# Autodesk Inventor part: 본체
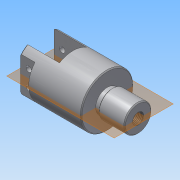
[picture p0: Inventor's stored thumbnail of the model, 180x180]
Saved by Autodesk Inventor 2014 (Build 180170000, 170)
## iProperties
Created: 2019-02
Part Number: 본체
Material: 알루미늄 6061
Document SubType Name: Modeling
Designer: net
Mass: 347.664 g
Surface Area: 292.638 cm^2
Volume: 128.289 cm^3
Density: 2.71 g/cm^3
Appearance: 알루미늄 - 평지
Author: net
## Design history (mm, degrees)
sketch "스케치1"
  geometry: L1 (0, 0)-(38, 0); L2 (0, 29)-(38, 29); L3 (38, 29)-(38, 0); L4 (0, 29)-(0, 14); L5 (0, 14)-(2.65, 14); L6 (2.65, 14)-(2.65, 17); L7 (2.65, 17)-(7.35, 17); L8 (7.35, 17)-(7.35, 14); L9 (7.35, 14)-(11.65, 14); L10 (11.65, 14)-(11.65, 17); L11 (11.65, 17)-(16.35, 17); L12 (16.35, 17)-(16.35, 14); L13 (20, 14)-(20, 16); L14 (20, 16)-(27, 16); L15 (27, 16)-(27, 0); L16 (5, 17)-(5, 0); L17 (14, 17)-(14, 0); L18 (16.35, 14)-(20, 14)
  constraints: 36 end point, 7 parallel, 6 perpendicular, 4 point on line, 3 horizontal alignment, 2 collinear, 2 midpoint, 1 coincident, 1 horizontal, 1 vertical alignment
  dimensions: "d5" = 38 distance of L2.start L2.end; "d7" = 58 diameter of L2 L1; "d8" = 28 diameter of L5 L1; "d9" = 34 diameter of L7 L1; "d11" = 4.7 distance of L6.end L7.end; "d12" = 7 distance of L13.end L14.end; "d15" = 5 horizontal distance of L4.end L16.start; "d16" = 9 distance of L17.start L16.start; "d17" = 32 diameter of L14 L1; "d25" = 27 horizontal distance of L14.end L4.end; "d26" = 29 distance of L2.end L3.end
revolve "회전1" sketch "스케치1" stored, may be unused: angle "d6" = 90 deg
sketch "스케치3"
  geometry: C1 r 29 at (0, 0) reference; C2 r 13 at (0, 0)
  constraints: 1 centre point, 1 coincident
  dimensions: "d19" = 26 diameter of C2
extrude "돌출1" join sketch "스케치3" distance "d20" = 5; taper "d21" = 0 deg
sketch "스케치4"
  geometry: C1 r 13 at (0, 0) reference; C2 r 15 at (0, 0)
  constraints: 1 centre point, 1 coincident
  dimensions: "d22" = 30 diameter of C2
extrude "돌출2" join sketch "스케치4" distance "d23" = 29; taper "d24" = 0 deg
sketch "스케치6"
  geometry: C1 r 29 at (0, 0) reference; C2 r 14 at (0, 0) reference; C3 r 29 at (0, 0)
  constraints: 1 centre point, 1 coincident, 1 concentric
extrude "돌출3" join sketch "스케치6" distance "d27" = 36; taper "d28" = 0 deg
node "작업 평면1"
sketch "스케치7"
  geometry: L1 (-36, 15)-(0, 15); L2 (0, 15)-(0, -15); L3 (0, -15)-(-36, -15); L4 (-36, -15)-(-36, 15); L5 (-36, 29)-(-36, -29) reference; 2 further points
  constraints: 8 end point, 2 parallel, 1 horizontal, 1 horizontal alignment, 1 midpoint, 1 perpendicular, 1 point on line
  dimensions: "d29" = 30 distance of L3.end L1.start; "d30" = 36 distance of L1.start L1.end
extrude "돌출4" cut sketch "스케치7" stored distance "d31" = 36; taper "d32" = 0 deg
sketch "스케치8"
  geometry: L1 (-36, 29)-(-20, 29); L2 (-20, 29)-(-20, 22); L3 (-20, 22)-(-36, 22); L4 (-36, 22)-(-36, 29); L5 (-36, 29)-(-36, 15) reference; L6 (-36, 29)-(38, 29) reference; L7 (-36, -22)-(-20, -22); L8 (-20, -22)-(-20, -29); L9 (-20, -29)-(-36, -29); L10 (-36, -29)-(-36, -22); L11 (-36, -15)-(-36, -29) reference; L12 (-36, -29)-(38, -29) reference; 1 further point
  constraints: 16 end point, 4 parallel, 2 horizontal, 2 perpendicular, 1 collinear
  dimensions: "d33" = 16 distance of L1.start L1.end; "d34" = 16 distance of L9.end L8.end; "d36" = 44 distance of L7.start L3.end
extrude "돌출5" cut sketch "스케치8" stored distance "d37" = 36; taper "d38" = 0 deg
sketch "스케치9"
  geometry: L1 (16, -37.789)-(16, 0) reference; L2 (9, -9.894)-(9, -27.894); L3 (0, -37.789)-(0, 0) reference; C1 r 3 at (9, -9.894); C2 r 3 at (9, -27.894); 3 further points
  constraints: 2 centre point, 2 end point, 2 midpoint, 1 equal radius, 1 horizontal alignment, 1 parallel, 1 vertical alignment
  dimensions: "d74" = 6 diameter of C1; "d75" = 18 distance of L2.start L2.end; "d76" = 9 horizontal distance of L3.start L2.end
extrude "돌출6" cut sketch "스케치9" stored distance "d43" = 36; taper "d44" = 0 deg
sketch "스케치10"
  geometry: C1 r 15 at (0, 0) reference
hole "구멍1" sketch "스케치10" at (0, 0) diameter "d46" = 12.376; stored, may be unused: countersink angle "d50" = 90 deg, drill point angle "d52" = 118 deg; dims "d47" = 18, "d48" = 4, "d49" = 2, "d51" = 22
node "작업 평면2"
sketch "스케치11"
  geometry: C1 r 4 at (0, 0); 1 further point
  constraints: 1 centre point, 1 coincident
  dimensions: "d54" = 8 diameter of C1
extrude "돌출7" cut sketch "스케치11" distance "d55" = 23; taper "d56" = 0 deg
node "작업 평면3"
sketch "스케치12"
  geometry: L1 (7, -5)-(-33, -5); L2 (-33, -5)-(-33, 5); L3 (-33, 5)-(7, 5); L4 (7, 5)-(7, -5); L5 (-38, 29)-(-38, -29) reference; 2 further points
  constraints: 8 end point, 2 parallel, 1 horizontal, 1 horizontal alignment, 1 midpoint, 1 perpendicular
  dimensions: "d58" = 10 distance of L3.end L1.start; "d59" = 40 distance of L1.start L1.end; "d60" = 5 distance from line of L5 L1.end
extrude "돌출8" join sketch "스케치12" stored distance "d61" = 23; taper "d62" = 0 deg
node "작업 평면4"
sketch "스케치13"
  geometry: L1 (7, 5)-(7, -5) reference; 2 further points
  constraints: 1 horizontal alignment, 1 other
  dimensions: "d64" = 20 distance from line of point (-13, 0) L1
feature "엠보싱1" sketch "스케치13" dims "d5" = 38, "d7" = 58, "d8" = 28, "d9" = 34, "d11" = 4.7, "d12" = 7, "d15" = 5, "d16" = 9, "d17" = 32, "d25" = 27, "d26" = 29, "d65" = 0.5, "d66" = 0
chamfer "모따기1" distance "d67" = 1; stored, may be unused: second distance "d68" = 2, angle "d69" = 45 deg
chamfer "모따기2" distance "d70" = 1; stored, may be unused: second distance "d71" = 2, angle "d72" = 45 deg
fillet "모깎기2" dims "d73" = 0.8
node "작업 평면5"
sketch "스케치14"
  geometry: 1 further point
chamfer "모따기3" distance "d78" = 1; stored, may be unused: second distance "d79" = 2, angle "d80" = 45 deg
chamfer "모따기4" distance "d81" = 1; stored, may be unused: second distance "d82" = 2, angle "d83" = 45 deg
node "솔리드1"
other parameters: "d53" = 27, "d63" = 5
